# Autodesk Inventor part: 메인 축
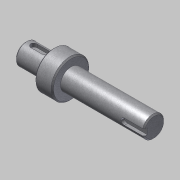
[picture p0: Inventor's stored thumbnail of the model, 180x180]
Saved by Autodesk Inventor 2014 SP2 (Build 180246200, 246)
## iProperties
Created: 2016-04
Part Number: 메인 축
Document SubType Name: Modeling
Designer: mdu
Density: 7.86 g/cm^3
Mass: 230.24 g
Surface Area: 74.3518 cm^2
Volume: 29.2926 cm^3
Material: 강철, 연강
Appearance: 금속-강(스테인리스, 브러시됨)
Author: mdu
Revision Number: 1
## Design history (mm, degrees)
sketch "스케치1"
  geometry: L1 (10.497, -57.5)-(112.497, -57.5); L2 (10.497, -66)-(32.497, -66); L3 (32.497, -72.5)-(46.5, -72.5); L4 (46.5, -66)-(112.497, -66); L5 (112.497, -66)-(112.497, -57.5); L6 (10.497, -66)-(10.497, -57.5); L7 (46.5, -69.749)-(46.5, -45.251) reference; L8 (46.5, -72.5)-(46.5, -66); L9 (32.497, -72.5)-(32.497, -66); L10 (32.497, -35)-(32.497, -80) reference; 3 further points
  constraints: 16 end point, 3 point on line, 2 parallel, 2 perpendicular, 1 collinear, 1 horizontal, 1 midpoint
  dimensions: "d0" = 17 diameter of L4 L1; "d1" = 30 diameter of L3 L1; "d2" = 22 distance of L2.start L2.end; "d3" = 65.99692 distance of L4.start L4.end (derived); "d5" = 17 diameter of L2 L1; "d19" = 80 distance between parallel lines of L5 L9
revolve "회전1" sketch "스케치1" stored, may be unused: angle "d4" = 90 deg
chamfer "모따기1" distance "d6" = 1; stored, may be unused: second distance "d7" = 2, angle "d8" = 45 deg
node "작업 평면1"
sketch "스케치2"
  geometry: L1 (-11, -7.5)-(-11, 7.5) reference; L2 (-4.5, 2.5)-(4.5, 2.5); L3 (4.5, -2.5)-(-4.5, -2.5); A1 r 2.5 centre (4.5, 0) between (4.5, -2.5) and (4.5, 2.5); A2 r 2.5 centre (-4.5, 0) between (-4.5, 2.5) and (-4.5, -2.5); 2 further points
  constraints: 4 end point, 4 point on circle, 4 tangent, 2 centre point, 1 horizontal alignment, 1 midpoint, 1 parallel, 1 perpendicular
  dimensions: "d9" = 5 distance between parallel lines of L3 L2; "d10" = 14 dimension on A1 A2; "d11" = 4 distance edge to line of A2 L1
extrude "돌출1" cut sketch "스케치2" distance "d12" = 3; taper "d13" = 0 deg
node "작업 평면2"
sketch "스케치3"
  geometry: L1 (32.998, 7.5)-(32.998, -7.5) reference; L2 (32.998, 2.5)-(17.498, 2.5); L3 (17.498, -2.5)-(32.998, -2.5); A1 r 2.5 centre (17.498, 0) between (17.498, 2.5) and (17.498, -2.5); 2 further points
  constraints: 4 end point, 2 perpendicular, 2 point on circle, 2 point on line, 2 tangent, 1 centre point, 1 horizontal alignment, 1 midpoint
  dimensions: "d14" = 5 distance between parallel lines of L3 L2; "d15" = 18 dimension on A1 L1
extrude "돌출2" cut sketch "스케치3" distance "d16" = 3; taper "d17" = 0 deg
node "솔리드1"
node "참조4"
node "참조5"
